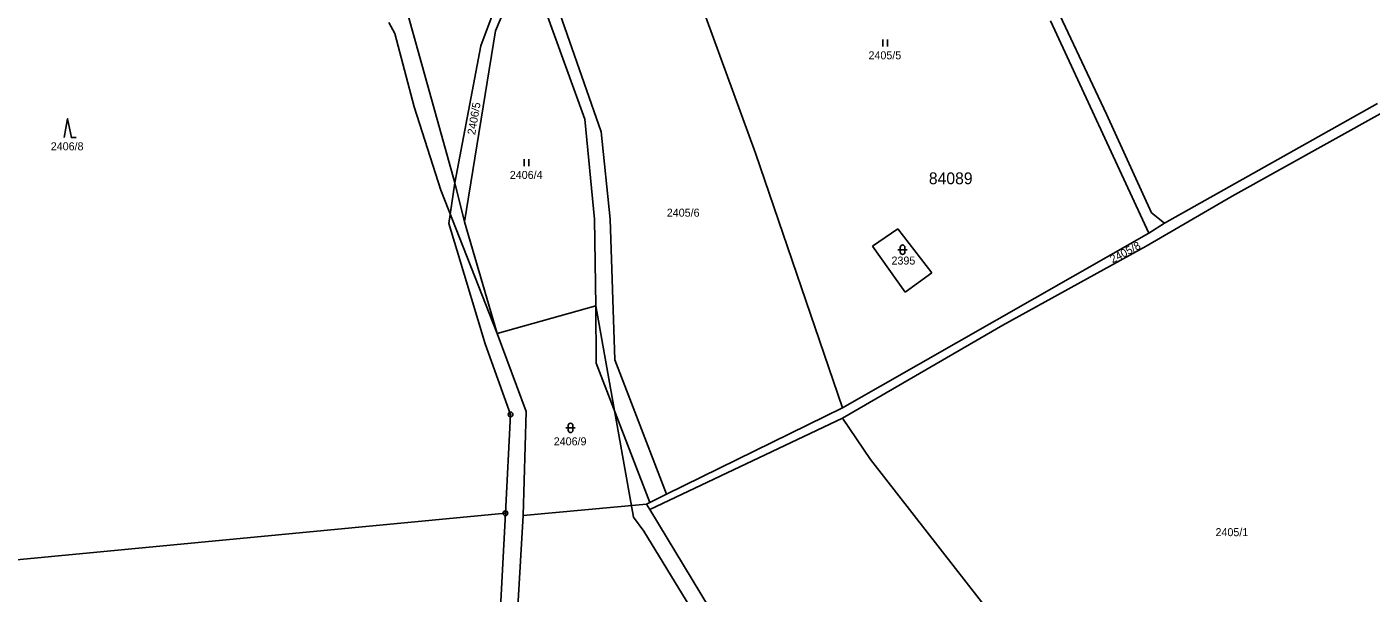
# Model space of a CAD drawing. Extents: x -439246 to -433691, y -1130252 to -1121148.
# Drawn here: x -437037 to -436751.4, y -1126545.9 to -1126425.6 of the extents above; entities that cross this region are included whole.
import ezdxf

# ---------------------------------------------------------------- set-up
doc = ezdxf.new("R2010")
doc.units = 0
for name, color, linetype in [('Vrstva 1', 7, 'Continuous'), ('Vrstva 18', 7, 'Continuous'), ('Vrstva 24', 7, 'Continuous'), ('Vrstva 25', 7, 'Continuous'), ('Vrstva 52', 7, 'Continuous'), ('Vrstva 53', 7, 'Continuous')]:
    doc.layers.add(name, color=color, linetype=linetype)

msp = doc.modelspace()

# ---------------------------------------------------------------- linework, layer by layer
at = {"layer": 'Vrstva 1'}
for points in [[(-436900.34, -1126402.69), (-436882.21, -1126452.45)], [(-436932.77, -1126408.73), (-436940.54, -1126429.66)], [(-436937.41, -1126426.47), (-436931.37, -1126411.97)], [(-436925.81, -1126416.83), (-436915.02, -1126447.88)], [(-436820.45, -1126416.89), (-436807.58, -1126444.12)], [(-436946.05, -1126458.72), (-436956.83, -1126420.11)], [(-436926.93, -1126421.75), (-436918.48, -1126445.17)], [(-436944.03, -1126467.03), (-436937.41, -1126426.47)], [(-436819.5, -1126424.34), (-436798.59, -1126469.43)], [(-436940.54, -1126429.66), (-436946.05, -1126458.72)], [(-436807.58, -1126444.12), (-436798.02, -1126465.11)], [(-436795.27, -1126467.3), (-436750.05, -1126441.88)], [(-436780.93, -1126461.53), (-436749.46, -1126444.06)], [(-436918.48, -1126445.17), (-436916.38, -1126466.44)], [(-436915.02, -1126447.88), (-436913.1, -1126466.43)], [(-436882.21, -1126452.45), (-436863.74, -1126506.49)], [(-436947.37, -1126467.34), (-436946.05, -1126458.72)], [(-436946.05, -1126458.72), (-436944.03, -1126467.03)], [(-436799.2, -1126472.2), (-436780.93, -1126461.53)], [(-436944.03, -1126467.03), (-436937.11, -1126490.74)], [(-436916.38, -1126466.44), (-436916.09, -1126484.85)], [(-436913.1, -1126466.43), (-436912.12, -1126496.35)], [(-436798.02, -1126465.11), (-436795.27, -1126467.3)], [(-436945.69, -1126472.99), (-436947.37, -1126467.34)], [(-436863.74, -1126506.49), (-436798.59, -1126469.43)], [(-436851.92, -1126468.53), (-436857.35, -1126472.21)], [(-436844.71, -1126477.85), (-436851.92, -1126468.53)], [(-436798.59, -1126469.43), (-436795.27, -1126467.3)], [(-436857.35, -1126472.21), (-436850.4, -1126481.93)], [(-436829.65, -1126488.96), (-436799.2, -1126472.2)], [(-436939.63, -1126492.96), (-436945.69, -1126472.99)], [(-436850.4, -1126481.93), (-436844.71, -1126477.85)], [(-436937.11, -1126490.74), (-436916.09, -1126484.85)], [(-436916.09, -1126484.85), (-436916.03, -1126497.02)], [(-436863.7, -1126508.72), (-436829.65, -1126488.96)], [(-436937.11, -1126490.74), (-436930.93, -1126507.27)], [(-436934.24, -1126507.92), (-436939.63, -1126492.96)], [(-436916.03, -1126497.02), (-436904.63, -1126526.6)], [(-436912.12, -1126496.35), (-436901.08, -1126524.85)], [(-436901.08, -1126524.85), (-436863.74, -1126506.49)], [(-436935.33, -1126528.93), (-436934.24, -1126507.92)], [(-436930.93, -1126507.27), (-436931.55, -1126529.37)], [(-436904.68, -1126528.12), (-436863.7, -1126508.72)], [(-436863.7, -1126508.72), (-436857.73, -1126517.52)], [(-436857.73, -1126517.52), (-436778.24, -1126619.42)], [(-436931.55, -1126529.37), (-436905.38, -1126526.97)], [(-436905.38, -1126526.97), (-436904.63, -1126526.6)], [(-436905.38, -1126526.97), (-436904.68, -1126528.12)], [(-436904.63, -1126526.6), (-436901.08, -1126524.85)], [(-437097.15, -1126544.31), (-436935.33, -1126528.93)], [(-436936.66, -1126554.31), (-436935.33, -1126528.93)], [(-436931.55, -1126529.37), (-436932.71, -1126548.69)], [(-436904.68, -1126528.12), (-436884.83, -1126560.88)]]:
    msp.add_lwpolyline(points, dxfattribs=at)
at = {"layer": 'Vrstva 24'}
for centre, radius in [((-436934.24, -1126507.92), 0.5), ((-436934.24, -1126507.92), 0.1), ((-436935.33, -1126528.93), 0.5), ((-436935.33, -1126528.93), 0.1)]:
    msp.add_circle(centre, radius, dxfattribs=at)
at = {"layer": 'Vrstva 25'}
for p, q in [((-436855.17, -1126429.79), (-436855.17, -1126428.29)), ((-436854.17, -1126429.79), (-436854.17, -1126428.29)), ((-436931.34, -1126455.2), (-436931.34, -1126453.7)), ((-436930.34, -1126455.2), (-436930.34, -1126453.7)), ((-436851.44, -1126473.43), (-436851.44, -1126472.43)), ((-436850.44, -1126472.43), (-436850.44, -1126473.43)), ((-436851.94, -1126472.93), (-436849.94, -1126472.93)), ((-436922.49, -1126510.79), (-436920.49, -1126510.79)), ((-436921.99, -1126511.29), (-436921.99, -1126510.29)), ((-436920.99, -1126510.29), (-436920.99, -1126511.29))]:
    msp.add_line(p, q, dxfattribs=at)
msp.add_lwpolyline([(-437029.07, -1126449.12), (-437028.37, -1126445.12), (-437027.57, -1126449.12), (-437026.57, -1126449.12)], dxfattribs=at)
for centre, start, end in [((-436850.94, -1126472.43), 0, 180), ((-436850.94, -1126473.43), 180, 0), ((-436921.49, -1126510.29), 0, 180), ((-436921.49, -1126511.29), 180, 0)]:
    msp.add_arc(centre, 0.5, start, end, dxfattribs=at)
at = {"layer": 'Vrstva 52'}
msp.add_lwpolyline([(-436960.08, -1126424.7), (-436958.8, -1126427.04), (-436954.75, -1126442.59), (-436949.05, -1126460.29), (-436937.11, -1126490.74), (-436916.09, -1126484.85), (-436908.14, -1126529.73), (-436905.93, -1126532.72), (-436886.35, -1126564.75)], dxfattribs=at)

# ---------------------------------------------------------------- texts
at = {"layer": 'Vrstva 18'}
for s, p in [('2405/5', (-436858.18, -1126432.49)), ('2406/8', (-437031.94, -1126451.82)), ('2406/4', (-436934.4, -1126457.9)), ('2405/6', (-436901.04, -1126465.92)), ('2395', (-436853.29, -1126476.09)), ('2406/9', (-436925.06, -1126514.49)), ('2405/1', (-436784.44, -1126533.78))]:
    msp.add_text(s, height=1.7, dxfattribs=at).set_placement(p)
for s, rotation, p in [('2406/5', 80.227, (-436941.78, -1126448.63)), ('2405/8', 28.0026, (-436806.31, -1126475.85))]:
    msp.add_text(s, height=1.7, rotation=rotation, dxfattribs=at).set_placement(p)
at = {"layer": 'Vrstva 53'}
msp.add_text('84089', height=2.5, dxfattribs=at).set_placement((-436845.36, -1126459.02))

doc.saveas('drawing.dxf')
